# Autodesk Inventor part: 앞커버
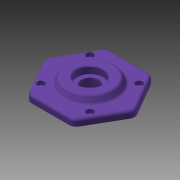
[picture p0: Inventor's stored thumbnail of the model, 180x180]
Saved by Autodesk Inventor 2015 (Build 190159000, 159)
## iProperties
Created: 2013-02
Part Number: 앞커버
Document SubType Name: Modeling
Density: 1 g/cm^3
Material: 일반
Appearance: 보라색
Author: 한국산업디자인학원[gmhk.co.kr]
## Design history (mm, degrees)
sketch "스케치1" dims "d37" = 105
  geometry: L1 (28.559, 41.466)-(50.191, 4); L2 (50.191, -4)-(28.559, -41.466); L3 (21.631, -45.466)-(-21.631, -45.466); L4 (-28.559, -41.466)-(-50.191, -4); L5 (-50.191, 4)-(-28.559, 41.466); L6 (-21.631, 45.466)-(21.631, 45.466); C1 r 30 at (0, 0); A1 r 8 centre (-43.262, 0) between (-50.191, 4) and (-50.191, -4); A2 r 8 centre (-21.631, 37.466) between (-21.631, 45.466) and (-28.559, 41.466); A3 r 8 centre (21.631, 37.466) between (28.559, 41.466) and (21.631, 45.466); A4 r 8 centre (43.262, 0) between (50.191, -4) and (50.191, 4); A5 r 8 centre (21.631, -37.466) between (21.631, -45.466) and (28.559, -41.466); A6 r 8 centre (-21.631, -37.466) between (-28.559, -41.466) and (-21.631, -45.466); 9 further points
  constraints: 12 end point, 12 point on circle, 12 point on line, 12 tangent, 7 centre point, 5 equal radius, 3 coincident, 1 horizontal, 16 other
  dimensions: "d40" = 8 radius of A1; "d41" = 60 diameter of C1
extrude "돌출1" new body sketch "스케치1" distance "d0" = 8; taper "d1" = 0 deg
sketch "스케치2"
  geometry: C1 r 30 at (0, 0); 1 further point
  constraints: 1 centre point, 1 coincident
  dimensions: "d2" = 60 diameter of C1
extrude "돌출2" join sketch "스케치2" distance "d3" = 7; taper "d4" = -30 deg
hole "구멍1" diameter "d7" = 20; stored, may be unused: countersink angle "d11" = 90 deg, drill point angle "d13" = 118 deg; dims "d8" = 6, "d9" = 30, "d10" = 8.3, "d12" = 20, "d52" = 10, "d53" = 10
sketch "스케치3"
  geometry: L1 (-28.284, 28.284)-(0, 0); L2 (0, 0)-(0, 40); L3 (0, 0)-(28.284, 28.284); L4 (0, 0)-(28.284, -28.284); L5 (0, 0)-(-28.284, -28.284); C1 r 1.621 at (28.284, 28.284); C2 r 1.621 at (-28.284, 28.284); C3 r 1.621 at (-28.284, -28.284); C4 r 1.621 at (28.284, -28.284); C5 r 10 at (0, 0) reference; A1 r 40 centre (0, 0) between (28.284, 28.284) and (-28.284, 28.284)
  constraints: 10 end point, 5 centre point, 3 perpendicular, 3 point on circle, 1 coincident, 1 vertical
  dimensions: "d48" = 80 diameter of A1; "d50" = 45 deg angle of L2 L1
hole "구멍2" sketch "스케치3" at (28.284, 28.284), (28.284, -28.284), (-28.284, -28.284), (-28.284, 28.284) diameter "d14" = 4.5; stored, may be unused: countersink angle "d18" = 90 deg, drill point angle "d20" = 118 deg; dims "d15" = 6, "d16" = 8, "d17" = 4.4, "d19" = 20
extrude "돌출3" join sketch "스케치1" distance "d21" = 12; taper "d22" = 0 deg
hole "구멍3" diameter "d25" = 30; stored, may be unused: countersink angle "d29" = 90 deg, drill point angle "d31" = 0 deg; dims "d26" = 6, "d27" = 40, "d28" = 12, "d30" = 15, "d42" = 10, "d43" = 10
fillet "모깎기1" dims "d32" = 3, "d33" = 0.3
chamfer "모따기1" distance "d34" = 1; stored, may be unused: second distance "d35" = 2, angle "d36" = 45 deg
chamfer "모따기2" distance "d44" = 1; stored, may be unused: second distance "d45" = 2, angle "d46" = 45 deg
fillet "모깎기2" dims "d47" = 3
fillet "모깎기3" dims "d54" = 0.6
node "솔리드1"
